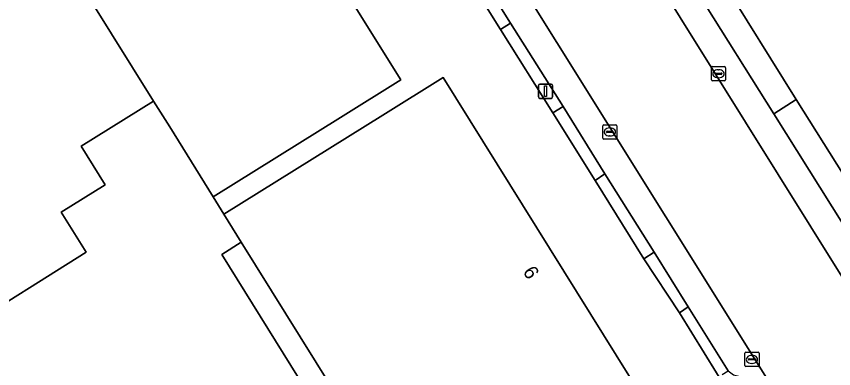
# Model space of a CAD drawing. Extents: x 158455 to 159797, y 387218 to 388672.
# Drawn here: x 158705 to 158762.6, y 387796.4 to 387821.1 of the extents above; entities that cross this region are included whole.
import ezdxf

# ---------------------------------------------------------------- set-up
doc = ezdxf.new("R2010")
doc.units = 0
for name, color, linetype in [('IMGEO_Erf', 7, 'Continuous'), ('IMGEO_Kolk', 7, 'Continuous'), ('IMGEO_Lichtmast', 7, 'Continuous'), ('IMGEO_Pand', 7, 'Continuous'), ('IMGEO_Pand_nummerreeks', 7, 'Continuous'), ('IMGEO_Parkeervlak_open', 7, 'Continuous'), ('IMGEO_Rijbaan_lokaal_gesloten', 7, 'Continuous'), ('IMGEO_Voetpad_open', 7, 'Continuous')]:
    doc.layers.add(name, color=color, linetype=linetype)

msp = doc.modelspace()

# ---------------------------------------------------------------- linework, layer by layer
at = {"layer": 'IMGEO_Erf'}
for points in [[(158728.733, 387865.314), (158743.767, 387841.201), (158748.891, 387832.962), (158754.689, 387823.696), (158759.914, 387815.287), (158768.898, 387801.005)], [(158756.93, 387791.852), (158751.714, 387800.276), (158749.206, 387804.072), (158745.778, 387809.594), (158742.791, 387814.338), (158739.108, 387820.198), (158721.653, 387848.076), (158717.423, 387855.013)], [(158721.98, 387832.89), (158732.099, 387816.668), (158727.857, 387814.022), (158718.906, 387808.438), (158719.649, 387807.206), (158730.844, 387814.188), (158735.086, 387816.834), (158751.068, 387791.209), (158735.631, 387781.581), (158738.754, 387776.575), (158717.649, 387763.184), (158705.955, 387781.931), (158710.198, 387784.578), (158727.162, 387795.16), (158720.877, 387805.237), (158719.499, 387804.377), (158724.907, 387795.706), (158709.281, 387785.958), (158705.038, 387783.311)], [(158701.131, 387799.023), (158709.969, 387804.536), (158708.207, 387807.361), (158711.297, 387809.289), (158709.613, 387811.988), (158714.709, 387815.167), (158708.787, 387824.66)]]:
    msp.add_lwpolyline(points, dxfattribs=at)
at = {"layer": 'IMGEO_Kolk'}
for p, q in [((158753.956, 387816.664), (158753.956, 387817.516)), ((158754.031, 387817.59), (158754.883, 387817.59)), ((158754.957, 387817.516), (158754.957, 387816.664)), ((158754.215, 387817.084), (158754.215, 387817.096)), ((158754.653, 387817.047), (158754.255, 387817.047)), ((158754.258, 387817.133), (158754.656, 387817.133)), ((158754.444, 387817.37), (158754.469, 387817.37)), ((158754.699, 387817.096), (158754.699, 387817.084)), ((158754.883, 387816.59), (158754.031, 387816.59)), ((158754.467, 387816.81), (158754.442, 387816.81)), ((158746.386, 387813.497), (158747.238, 387813.497)), ((158746.311, 387812.571), (158746.311, 387813.423)), ((158746.57, 387812.991), (158746.57, 387813.003)), ((158747.008, 387812.954), (158746.61, 387812.954)), ((158746.613, 387813.04), (158747.011, 387813.04)), ((158746.799, 387813.277), (158746.824, 387813.277)), ((158747.054, 387813.003), (158747.054, 387812.991)), ((158747.312, 387813.423), (158747.312, 387812.571)), ((158747.238, 387812.497), (158746.386, 387812.497)), ((158746.822, 387812.717), (158746.797, 387812.717)), ((158756.311, 387796.58), (158756.311, 387797.432)), ((158756.386, 387797.506), (158757.238, 387797.506)), ((158757.312, 387797.432), (158757.312, 387796.58)), ((158756.57, 387797), (158756.57, 387797.012)), ((158757.008, 387796.963), (158756.61, 387796.963)), ((158756.613, 387797.049), (158757.011, 387797.049)), ((158756.799, 387797.286), (158756.824, 387797.286)), ((158757.054, 387797.012), (158757.054, 387797)), ((158757.238, 387796.506), (158756.386, 387796.506)), ((158756.822, 387796.726), (158756.797, 387796.726))]:
    msp.add_line(p, q, dxfattribs=at)
for points in [[(158753.956, 387816.664), (158753.956, 387817.516)], [(158754.031, 387817.59), (158754.883, 387817.59)], [(158754.957, 387817.516), (158754.957, 387816.664)], [(158754.883, 387816.59), (158754.031, 387816.59)], [(158746.386, 387813.497), (158747.238, 387813.497)], [(158746.311, 387812.571), (158746.311, 387813.423)], [(158747.312, 387813.423), (158747.312, 387812.571)], [(158747.238, 387812.497), (158746.386, 387812.497)], [(158756.311, 387796.58), (158756.311, 387797.432)], [(158756.386, 387797.506), (158757.238, 387797.506)], [(158757.312, 387797.432), (158757.312, 387796.58)], [(158757.238, 387796.506), (158756.386, 387796.506)]]:
    msp.add_lwpolyline(points, dxfattribs=at)
for centre, radius, start, end in [((158754.033, 387817.514), 0.0765, 91.55205, 178.44795), ((158754.033, 387817.514), 0.0765, 91.55205, 178.44795), ((158754.881, 387817.514), 0.0765, 1.55205, 88.44795), ((158754.881, 387817.514), 0.0765, 1.55205, 88.44795), ((158754.255, 387817.093), 0.0403, 85.87752, 175.75265), ((158754.252, 387817.083), 0.0366, 178.93798, 274.71019), ((158754.656, 387817.09), 0.043, 264.86636, 352.45326), ((158754.66, 387817.095), 0.0386, 1.73085, 96.63898), ((158754.033, 387816.666), 0.0765, 181.55205, 268.44795), ((158754.033, 387816.666), 0.0765, 181.55205, 268.44795), ((158754.881, 387816.666), 0.0765, 271.55205, 358.44795), ((158754.881, 387816.666), 0.0765, 271.55205, 358.44795), ((158746.388, 387813.421), 0.0765, 91.55205, 178.44795), ((158746.388, 387813.421), 0.0765, 91.55205, 178.44795), ((158747.236, 387813.421), 0.0765, 1.55205, 88.44795), ((158747.236, 387813.421), 0.0765, 1.55205, 88.44795), ((158746.61, 387813), 0.0403, 85.87752, 175.75265), ((158746.607, 387812.99), 0.0366, 178.93798, 274.71019), ((158747.011, 387812.997), 0.043, 264.86636, 352.45326), ((158747.015, 387813.002), 0.0386, 1.73085, 96.63898), ((158746.388, 387812.573), 0.0765, 181.55205, 268.44795), ((158746.388, 387812.573), 0.0765, 181.55205, 268.44795), ((158747.236, 387812.573), 0.0765, 271.55205, 358.44795), ((158747.236, 387812.573), 0.0765, 271.55205, 358.44795), ((158756.388, 387797.43), 0.0765, 91.55205, 178.44795), ((158756.388, 387797.43), 0.0765, 91.55205, 178.44795), ((158757.236, 387797.43), 0.0765, 1.55205, 88.44795), ((158757.236, 387797.43), 0.0765, 1.55205, 88.44795), ((158756.61, 387797.009), 0.0403, 85.87752, 175.75265), ((158756.607, 387796.999), 0.0366, 178.93798, 274.71019), ((158757.011, 387797.006), 0.043, 264.86636, 352.45326), ((158757.015, 387797.011), 0.0386, 1.73085, 96.63898), ((158756.388, 387796.582), 0.0765, 181.55205, 268.44795), ((158756.388, 387796.582), 0.0765, 181.55205, 268.44795), ((158757.236, 387796.582), 0.0765, 271.55205, 358.44795), ((158757.236, 387796.582), 0.0765, 271.55205, 358.44795)]:
    msp.add_arc(centre, radius, start, end, dxfattribs=at)
for centre, major_axis, ratio, start_param, end_param in [((158754.443, 387817.09), (-0.387, 0.002), 0.722429, 4.712389, 7.853982), ((158754.468, 387817.09), (-0.39, 0.002), 0.717154, 1.570796, 4.712389), ((158746.798, 387812.997), (-0.387, 0.002), 0.722429, 4.712389, 7.853982), ((158746.823, 387812.997), (-0.39, 0.002), 0.717154, 1.570796, 4.712389), ((158756.798, 387797.006), (-0.387, 0.002), 0.722429, 4.712389, 7.853982), ((158756.823, 387797.006), (-0.39, 0.002), 0.717154, 1.570796, 4.712389)]:
    msp.add_ellipse(centre, major_axis=major_axis, ratio=ratio, start_param=start_param, end_param=end_param, dxfattribs=at)
at = {"layer": 'IMGEO_Lichtmast'}
for p, q in [((158741.882, 387816.358), (158742.672, 387816.358)), ((158742.672, 387816.358), (158741.882, 387816.358)), ((158741.782, 387815.458), (158741.782, 387816.258)), ((158741.782, 387816.258), (158741.782, 387815.458)), ((158742.772, 387816.258), (158742.772, 387815.458)), ((158742.772, 387815.458), (158742.772, 387816.258)), ((158742.672, 387815.358), (158741.882, 387815.358)), ((158741.882, 387815.358), (158742.672, 387815.358))]:
    msp.add_line(p, q, dxfattribs=at)
msp.add_lwpolyline([(158742.202, 387816.233), (158742.352, 387816.233), (158742.352, 387815.483), (158742.202, 387815.483), (158742.202, 387816.233)], dxfattribs=at)
for centre, start, end in [((158741.882, 387816.258), 90, 180), ((158741.882, 387816.258), 90, 180), ((158742.672, 387816.258), 0, 90), ((158742.672, 387816.258), 360, 90), ((158741.882, 387815.458), 180, 270), ((158741.882, 387815.458), 180, 270), ((158742.672, 387815.458), 270, 0), ((158742.672, 387815.458), 270, 0)]:
    msp.add_arc(centre, 0.1, start, end, dxfattribs=at)
at = {"layer": 'IMGEO_Pand'}
for points in [[(158718.906, 387808.438), (158727.857, 387814.022), (158732.099, 387816.668), (158721.98, 387832.89), (158717.738, 387830.244), (158708.787, 387824.66), (158714.709, 387815.167), (158715.842, 387813.35)], [(158720.877, 387805.237), (158727.162, 387795.16), (158735.631, 387781.581), (158751.068, 387791.209), (158735.086, 387816.834), (158730.844, 387814.188), (158719.649, 387807.206)], [(158718.906, 387808.438), (158715.842, 387813.35), (158714.709, 387815.167), (158709.613, 387811.988), (158711.297, 387809.289), (158708.207, 387807.361), (158709.969, 387804.536), (158701.131, 387799.023), (158696.888, 387796.376), (158705.038, 387783.311), (158709.281, 387785.958), (158724.907, 387795.706), (158719.499, 387804.377), (158720.877, 387805.237), (158719.649, 387807.206)]]:
    msp.add_lwpolyline(points, close=True, dxfattribs=at)
at = {"layer": 'IMGEO_Parkeervlak_open'}
for points in [[(158726.354, 387861.718), (158765.551, 387798.969)], [(158765.358, 387800.383), (158765.761, 387802.161), (158765.684, 387802.572), (158758.354, 387814.271), (158753.083, 387822.684), (158747.281, 387831.975), (158742.164, 387840.209), (158729.75, 387860.062), (158729.422, 387860.387), (158727.644, 387860.794)], [(158758.415, 387794.78), (158719.943, 387856.262)], [(158720.172, 387855.003), (158719.794, 387853.011), (158719.845, 387852.55), (158722.344, 387848.558), (158739.823, 387820.649), (158743.518, 387814.783), (158746.466, 387810.055), (158749.932, 387804.541), (158752.321, 387800.693), (158755.129, 387796.205), (158755.51, 387795.922), (158757.317, 387795.475)]]:
    msp.add_lwpolyline(points, dxfattribs=at)
at = {"layer": 'IMGEO_Rijbaan_lokaal_gesloten'}
for points in [[(158765.551, 387798.969), (158726.354, 387861.718)], [(158718.649, 387858.075), (158719.943, 387856.262), (158758.415, 387794.78)]]:
    msp.add_lwpolyline(points, dxfattribs=at)
at = {"layer": 'IMGEO_Voetpad_open'}
for points in [[(158722.344, 387848.558), (158721.653, 387848.076), (158739.108, 387820.198), (158739.823, 387820.649)], [(158754.689, 387823.696), (158753.083, 387822.684), (158758.354, 387814.271), (158759.914, 387815.287)], [(158739.823, 387820.649), (158739.108, 387820.198), (158742.791, 387814.338), (158743.518, 387814.783)], [(158743.518, 387814.783), (158742.791, 387814.338), (158745.778, 387809.594), (158746.466, 387810.055)], [(158749.206, 387804.072), (158749.932, 387804.541), (158746.466, 387810.055), (158745.778, 387809.594)], [(158751.714, 387800.276), (158752.321, 387800.693), (158749.932, 387804.541), (158749.206, 387804.072)]]:
    msp.add_lwpolyline(points, close=True, dxfattribs=at)
for points in [[(158768.898, 387801.005), (158759.914, 387815.287), (158758.354, 387814.271), (158765.684, 387802.572), (158766.145, 387802.853)], [(158754.704, 387795.942), (158755.129, 387796.205), (158752.321, 387800.693), (158751.714, 387800.276), (158756.93, 387791.852)]]:
    msp.add_lwpolyline(points, dxfattribs=at)

# ---------------------------------------------------------------- texts
at = {"layer": 'IMGEO_Pand_nummerreeks'}
msp.add_text('6', height=1, rotation=301.95129, dxfattribs=at).set_placement((158740.657, 387803.177))

doc.saveas('drawing.dxf')
